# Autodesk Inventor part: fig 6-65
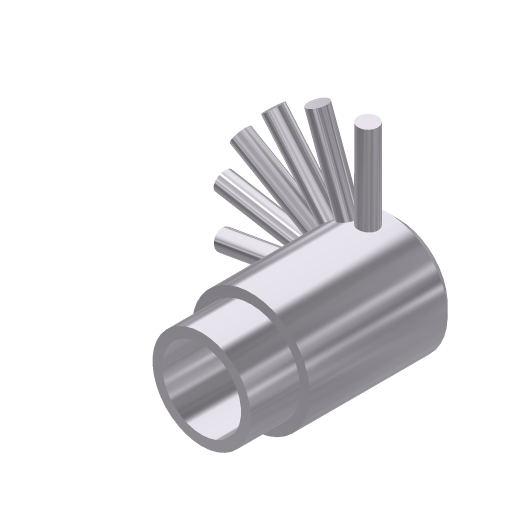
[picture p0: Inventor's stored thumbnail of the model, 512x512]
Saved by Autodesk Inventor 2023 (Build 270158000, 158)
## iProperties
Created: 2001-12
Part Number: fig 6-65
Document SubType Name: Modeling
Designer: Renu Muthoo
Density: 1 g/cm^3
Material: Generic
Appearance: Metal-AL-6061 (Polished)
Control State: 0
Master: False
Checked Out: False
Shininess: 77.0
Angle Display Precision: 2
Document Length Units: 11269
Document Angle Units: 11279
Document Time Units: 11290
Document Mass Units: 11283
Document Length Units Precision: 3
Document Angle Units Precision: 2
Compacted: True
Density: 0.0
Volumn: 0.0
Area: 0.0
PropertySet Name: Model Information
Author: Renu Muthoo
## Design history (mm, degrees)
sketch "Sketch2"
  geometry: L1 (-9.573, -4.327)-(-9.573, -5.327); L2 (-9.573, -5.327)-(-4.573, -5.327); L3 (-4.573, -5.327)-(-4.573, -6.327); L4 (-4.573, -6.327)-(9.427, -6.327); L5 (9.427, -6.327)-(10.427, -5.327); L6 (10.427, -5.327)-(10.427, -4.327); L7 (10.427, -4.327)-(-9.573, -4.327); L8 (-13.687, -0.327)-(14, -0.327)
  constraints: 16 end point, 5 parallel, 1 perpendicular, 1 vertical
  dimensions: "d9" = 20 distance of L6.end L1.start; "d10" = 5 distance of L1.end L2.end; "d11" = 12 diameter of L4 L8; "d12" = 10 diameter of L2 L8; "d13" = 8 diameter of L7 L8; "d14" = 45 deg angle of L5 L4; "d15" = 1 horizontal distance of L5.end L4.end
revolve "Revolution2" sketch "Sketch2" stored, may be unused: angle "d16" = 90 deg
workplane "Work Plane1"
workplane "Work Plane2"
sketch "Sketch3"
  geometry: L1 (-4, 8)-(4, 8) reference; C1 r 1 at (-0.098, 5)
  constraints: 1 centre point
  dimensions: "d18" = 3 distance from line of L1 C1.centre; "d19" = 2 diameter of C1
extrude "Extrusion1" join sketch "Sketch3" distance "d20" = 10; taper "d21" = 0 deg
pattern_circular "Circular Pattern3" dims angle "d29" = 20 deg
body "Solid1"
other parameters: "d17" = -1
